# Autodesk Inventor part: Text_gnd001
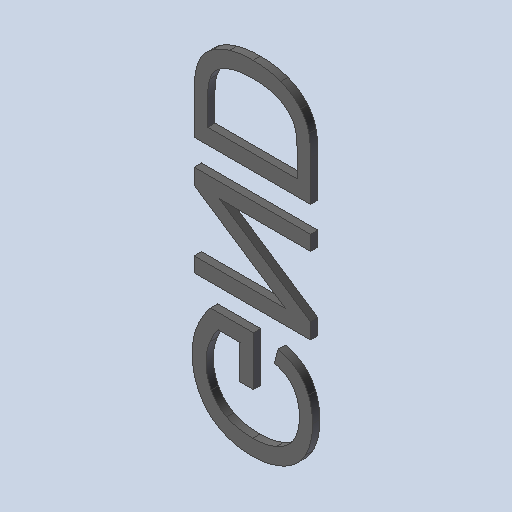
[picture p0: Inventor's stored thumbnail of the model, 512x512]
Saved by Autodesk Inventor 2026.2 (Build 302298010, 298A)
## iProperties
Created: 2026-10
Part Number: Text_gnd001
Material: Générique
Document SubType Name: Modeling
Designer: mel
Density: 1 g/cm^3
Appearance: Par défaut
Author: mel
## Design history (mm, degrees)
feature "Base1"
feature "Base2"
feature "Base3"
node "Solide1"
node "Solide2"
node "Solide3"
